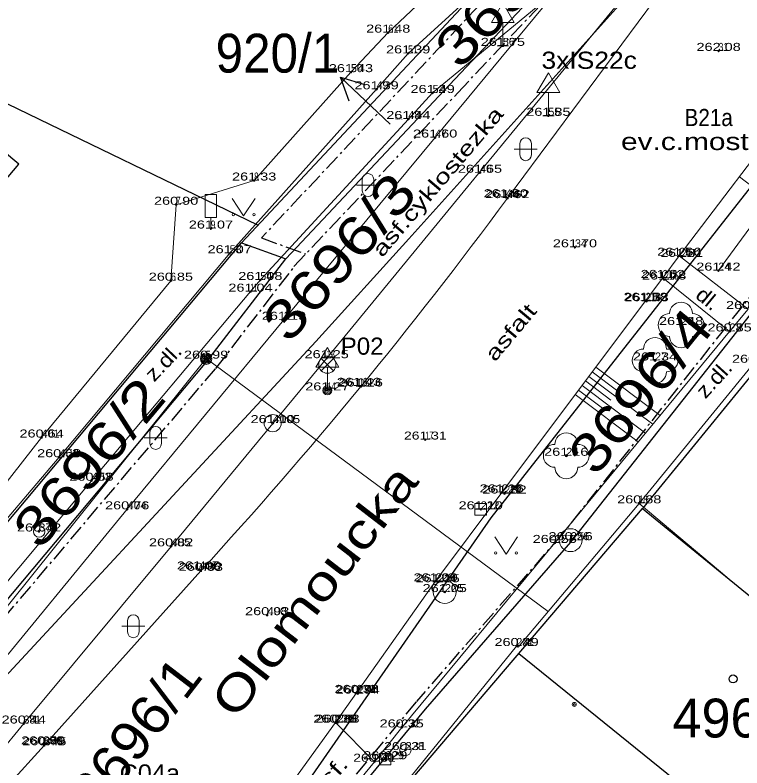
# Model space of a CAD drawing. Extents: x -568530 to -568223, y -1154101 to -1153740.
# Drawn here: x -568460.84 to -568429.07, y -1153975.43 to -1153942.5 of the extents above; entities that cross this region are included whole.
import ezdxf
from ezdxf.enums import TextEntityAlignment as Align

# ---------------------------------------------------------------- set-up
doc = ezdxf.new("R2010")
doc.units = 0
doc.header["$LTSCALE"] = 0.14
doc.header["$PDMODE"] = 32
doc.header["$PDSIZE"] = 0.07
doc.linetypes.add('DOT_DASHED', pattern=[7.7, 5, -1.2, 0.3, -1.2])
for name, color, linetype, lineweight in [('1', 7, 'Continuous', 25), ('10', 7, 'Continuous', 13), ('11', 7, 'Continuous', 13), ('12', 7, 'Continuous', 13), ('15', 7, 'Continuous', 13), ('21', 7, 'Continuous', 13), ('22', 7, 'Continuous', 13), ('23', 7, 'Continuous', 13), ('25', 7, 'Continuous', 13), ('27', 7, 'Continuous', 13), ('28', 7, 'Continuous', 13), ('33', 7, 'Continuous', 13), ('34', 7, 'Continuous', 13), ('36', 7, 'Continuous', 13), ('38', 7, 'Continuous', 13), ('39', 7, 'Continuous', 13), ('42', 7, 'Continuous', 13), ('5', 7, 'Continuous', 13), ('51', 7, 'Continuous', 13), ('6', 7, 'DOT_DASHED', 25), ('7', 7, 'Continuous', 13)]:
    doc.layers.add(name, color=color, linetype=linetype, lineweight=lineweight)
for name, color, linetype in [('13', 7, 'Continuous'), ('18', 7, 'Continuous'), ('19', 7, 'Continuous'), ('20', 7, 'Continuous'), ('40', 7, 'Continuous'), ('49', 7, 'Continuous')]:
    doc.layers.add(name, color=color, linetype=linetype)

msp = doc.modelspace()

# ---------------------------------------------------------------- linework, layer by layer
at = {"layer": '1'}
for p, q in [((-568450.23, -1153951.69), (-568463.93, -1153945.07)), ((-568450.95, -1153952.46), (-568449.01, -1153953.16)), ((-568443.46, -1153975.87), (-568433.42, -1153964.08)), ((-568438.82, -1153970.42), (-568429.77, -1153977.74))]:
    msp.add_line(p, q, dxfattribs=at)
for points in [[(-568415.28, -1153906.83), (-568416.25, -1153907.73), (-568417.28, -1153909.65), (-568429.7, -1153929.89), (-568430.98, -1153931.64), (-568432.38, -1153933.77), (-568434.43, -1153934.79), (-568436.25, -1153936.74), (-568450.95, -1153952.46)], [(-568474.2, -1153983.6), (-568452.46, -1153957.65), (-568449.01, -1153953.16), (-568441.85, -1153945.56), (-568434.01, -1153937.23), (-568430.2, -1153935.69), (-568428.09, -1153933.47), (-568426.88, -1153931.62), (-568414.57, -1153911.32), (-568413.31, -1153909.52)], [(-568421.22, -1153939.56), (-568428.14, -1153935.17), (-568430.26, -1153937.4), (-568443.63, -1153952.29), (-568447.7, -1153956.78), (-568470.49, -1153981.39)], [(-568416.35, -1153942.92), (-568421.22, -1153939.56), (-568427.43, -1153948.41), (-568440.04, -1153964.5), (-568454.41, -1153985.19), (-568457.74, -1153989.19)], [(-568465.85, -1153955.45), (-568463.4, -1153952.25), (-568460.68, -1153949.03), (-568464.54, -1153945.8), (-568464.79, -1153945.59), (-568466, -1153947.05)], [(-568421.83, -1153950.13), (-568423.36, -1153948.82), (-568436.57, -1153965.56)], [(-568421.83, -1153950.13), (-568427.7, -1153957.09), (-568433.42, -1153964.08), (-568426, -1153970.14), (-568416.24, -1153978.06), (-568413.96, -1153980.06), (-568408.2, -1153972.93), (-568413.31, -1153968.6), (-568420.22, -1153963.08), (-568427.7, -1153957.09)], [(-568498.47, -1153957.36), (-568472.48, -1153978.28), (-568467.49, -1153972.24), (-568464.36, -1153968.47), (-568450.95, -1153952.46)], [(-568436.57, -1153965.56), (-568442.92, -1153972.86), (-568448.69, -1153979.85), (-568458.57, -1153991.38), (-568456.99, -1153992.49)]]:
    msp.add_lwpolyline(points, dxfattribs=at)
at = {"layer": '10'}
for p, q in [((-568459.56, -1153974.44), (-568452.72, -1153966.81)), ((-568468.5, -1153984.3), (-568459.56, -1153974.44))]:
    msp.add_line(p, q, dxfattribs=at)
for points in [[(-568451.7, -1153980.29), (-568449.61, -1153977.28), (-568446.84, -1153973.45), (-568445.91, -1153972.15), (-568442.46, -1153967.27), (-568439.57, -1153963.38), (-568433.28, -1153955), (-568432.53, -1153954), (-568431.81, -1153953.03), (-568426.84, -1153946.5), (-568420.35, -1153937.98), (-568416.07, -1153932.32)], [(-568439.32, -1153950.51), (-568432.9, -1153941.84), (-568427.22, -1153934.12)]]:
    msp.add_lwpolyline(points, dxfattribs=at)
msp.add_arc((-568598.8003, -1153833.0615), 198.0609, 317.52333, 323.63038, dxfattribs=at)
at = {"layer": '11'}
for p, q in [((-568447.22, -1153957.51), (-568433.85, -1153941.21)), ((-568437.12, -1153941.38), (-568442.59, -1153945.91)), ((-568437.12, -1153941.38), (-568442.48, -1153947.86)), ((-568432.53, -1153954), (-568429.61, -1153956.34)), ((-568460.46, -1153973.49), (-568468.03, -1153982.68)), ((-568446.84, -1153973.45), (-568445.13, -1153975.16))]:
    msp.add_line(p, q, dxfattribs=at)
for points in [[(-568451.52, -1153952.97), (-568451.46, -1153952.92), (-568445.04, -1153945.75), (-568443.66, -1153944.18), (-568437.31, -1153938.38), (-568436.1, -1153937.25), (-568432.62, -1153934.09)], [(-568442.59, -1153945.91), (-568443.65, -1153947.05), (-568450.12, -1153954.09), (-568450.55, -1153954.6), (-568457.5, -1153962.87), (-568463.86, -1153970.48)], [(-568462.41, -1153971.99), (-568455.94, -1153964.12), (-568449.09, -1153955.83), (-568442.48, -1153947.86)], [(-568464.95, -1153968.94), (-568458.91, -1153961.84), (-568451.46, -1153952.92)], [(-568445.13, -1153975.16), (-568443.94, -1153973.66), (-568437.25, -1153965.59), (-568429.61, -1153956.34), (-568428.8, -1153955.36), (-568431.81, -1153953.03)], [(-568447.22, -1153957.51), (-568454.02, -1153965.74), (-568460.46, -1153973.49)], [(-568458.69, -1153991.53), (-568450.34, -1153981.46), (-568447.73, -1153978.32), (-568445.13, -1153975.16)]]:
    msp.add_lwpolyline(points, dxfattribs=at)
for p in [(-568444.53, -1153943.27), (-568439.52, -1153943.85), (-568443.66, -1153944.18), (-568430.09, -1153944.07), (-568446.16, -1153945), (-568445.04, -1153945.75), (-568442.59, -1153945.91), (-568443.65, -1153947.05), (-568437.53, -1153946.91), (-568442.48, -1153947.86), (-568440.52, -1153949.4), (-568450.39, -1153949.74), (-568439.39, -1153950.47), (-568439.32, -1153950.51), (-568453.8, -1153950.8), (-568452.28, -1153951.84), (-568436.37, -1153952.66), (-568451.46, -1153952.92), (-568431.81, -1153953.03), (-568431.7, -1153953.08), (-568430.1, -1153953.68), (-568454.03, -1153954.12), (-568450.12, -1153954.09), (-568432.53, -1153954), (-568432.47, -1153954.07), (-568450.55, -1153954.6), (-568433.28, -1153955), (-568433.24, -1153955.02), (-568449.09, -1153955.83), (-568431.73, -1153956.06), (-568429.61, -1153956.34), (-568452.49, -1153957.53), (-568447.22, -1153957.51), (-568432.87, -1153957.61), (-568445.81, -1153958.72), (-568447.19, -1153958.92), (-568445.73, -1153958.75), (-568459.68, -1153960.98), (-568442.91, -1153961.07), (-568458.91, -1153961.84), (-568436.75, -1153961.78), (-568457.5, -1153962.87), (-568439.57, -1153963.38), (-568439.45, -1153963.43), (-568433.56, -1153963.86), (-568455.94, -1153964.12), (-568440.49, -1153964.12), (-568459.79, -1153965.09), (-568437.25, -1153965.59), (-568436.56, -1153965.47), (-568454.02, -1153965.74), (-568452.8, -1153966.75), (-568452.72, -1153966.81), (-568442.46, -1153967.27), (-568442.37, -1153967.31), (-568442.06, -1153967.74), (-568449.82, -1153968.75), (-568438.92, -1153970.1), (-568445.91, -1153972.15), (-568445.86, -1153972.18), (-568460.46, -1153973.49), (-568446.84, -1153973.45), (-568446.75, -1153973.45), (-568443.94, -1153973.66), (-568459.61, -1153974.4), (-568459.56, -1153974.44), (-568443.78, -1153974.65), (-568445.13, -1153975.16), (-568444.66, -1153975.05)]:
    msp.add_point(p, dxfattribs=at)
at = {"layer": '15'}
for p, q in [((-568429.185, -1153949.58), (-568426.029, -1153951.982)), ((-568435.46, -1153957.905), (-568432.647, -1153960.017)), ((-568435.76, -1153958.305), (-568432.965, -1153960.403)), ((-568435.61, -1153958.105), (-568434.489, -1153958.947)), ((-568436.061, -1153958.705), (-568433.284, -1153960.788)), ((-568435.911, -1153958.505), (-568434.796, -1153959.341)), ((-568436.211, -1153958.904), (-568435.104, -1153959.735)), ((-568436.361, -1153959.104), (-568433.603, -1153961.174))]:
    msp.add_line(p, q, dxfattribs=at)
at = {"layer": '21'}
for radius in [0.375, 0.05]:
    msp.add_circle((-568449.58, -1153960.35), radius, dxfattribs=at)
at = {"layer": '22'}
for centre in [(-568431.73, -1153956.06), (-568432.87, -1153957.61), (-568436.75, -1153961.78)]:
    msp.add_circle(centre, 0.05, dxfattribs=at)
for centre, start, end in [((-568431.73, -1153955.56), 0, 180), ((-568432.23, -1153956.06), 90, 270), ((-568431.23, -1153956.06), 270, 90), ((-568432.87, -1153957.11), 0, 180), ((-568431.73, -1153956.56), 180, 0), ((-568433.37, -1153957.61), 90, 270), ((-568432.37, -1153957.61), 270, 90), ((-568432.87, -1153958.11), 180, 0), ((-568436.75, -1153961.28), 0, 180), ((-568437.25, -1153961.78), 90, 270), ((-568436.25, -1153961.78), 270, 90), ((-568436.75, -1153962.28), 180, 0)]:
    msp.add_arc(centre, 0.5, start, end, dxfattribs=at)
at = {"layer": '25', "lineweight": 25}
msp.add_line((-568444.44, -1153947.28), (-568446.623, -1153945.223), dxfattribs=at)
msp.add_lwpolyline([(-568446.238, -1153946.273), (-568446.623, -1153945.223), (-568445.552, -1153945.545)], dxfattribs=at)
at = {"layer": '25'}
for radius in [0.25, 0.2, 0.15, 0.1, 0.05]:
    msp.add_circle((-568452.49, -1153957.53), radius, dxfattribs=at)
at = {"layer": '25', "lineweight": 25}
msp.add_circle((-568429.46, -1153971.54), 0.175, dxfattribs=at)
at = {"layer": '27'}
for p, q in [((-568440.74, -1153964.12), (-568440.24, -1153964.12)), ((-568444.91, -1153975.05), (-568444.41, -1153975.05))]:
    msp.add_line(p, q, dxfattribs=at)
for points in [[(-568440.74, -1153964.37), (-568440.24, -1153964.37), (-568440.24, -1153963.87), (-568440.74, -1153963.87)], [(-568444.91, -1153975.3), (-568444.41, -1153975.3), (-568444.41, -1153974.8), (-568444.91, -1153974.8)]]:
    msp.add_lwpolyline(points, close=True, dxfattribs=at)
for centre in [(-568436.56, -1153965.47), (-568442.06, -1153967.74)]:
    msp.add_circle(centre, 0.5, dxfattribs=at)
at = {"layer": '28'}
for centre in [(-568459.79, -1153965.09), (-568443.78, -1153974.65)]:
    msp.add_circle(centre, 0.25, dxfattribs=at)
at = {"layer": '33'}
for p, q in [((-568447.455, -1153958.06), (-568446.925, -1153957.53)), ((-568447.455, -1153957.53), (-568446.925, -1153958.06)), ((-568447.19, -1153958.17), (-568447.19, -1153958.92))]:
    msp.add_line(p, q, dxfattribs=at)
for centre, radius in [((-568447.19, -1153957.795), 0.375), ((-568447.19, -1153958.92), 0.2), ((-568447.19, -1153958.92), 0.1445), ((-568447.19, -1153958.92), 0.0876)]:
    msp.add_circle(centre, radius, dxfattribs=at)
at = {"layer": '34'}
for p, q in [((-568439.52, -1153942.832), (-568439.52, -1153943.85)), ((-568439.77, -1153943.85), (-568439.27, -1153943.85)), ((-568437.53, -1153945.892), (-568437.53, -1153946.91)), ((-568437.78, -1153946.91), (-568437.28, -1153946.91)), ((-568447.19, -1153957.902), (-568447.19, -1153958.92))]:
    msp.add_line(p, q, dxfattribs=at)
for points in [[(-568440.02, -1153942.832), (-568439.02, -1153942.832), (-568439.52, -1153941.966)], [(-568438.03, -1153945.892), (-568437.03, -1153945.892), (-568437.53, -1153945.026)], [(-568447.69, -1153957.902), (-568446.69, -1153957.902), (-568447.19, -1153957.036)]]:
    msp.add_lwpolyline(points, close=True, dxfattribs=at)
at = {"layer": '36'}
for p, q in [((-568438.774, -1153948.121), (-568438.774, -1153948.621)), ((-568438.274, -1153948.121), (-568438.274, -1153948.621)), ((-568439.024, -1153948.371), (-568438.024, -1153948.371)), ((-568445.664, -1153949.686), (-568445.664, -1153950.186)), ((-568445.164, -1153949.686), (-568445.164, -1153950.186)), ((-568445.914, -1153949.936), (-568444.914, -1153949.936)), ((-568455.194, -1153960.997), (-568454.194, -1153960.997)), ((-568454.944, -1153960.747), (-568454.944, -1153961.247)), ((-568454.444, -1153960.747), (-568454.444, -1153961.247)), ((-568456.173, -1153969.235), (-568455.173, -1153969.235)), ((-568455.923, -1153968.985), (-568455.923, -1153969.485)), ((-568455.423, -1153968.985), (-568455.423, -1153969.485))]:
    msp.add_line(p, q, dxfattribs=at)
for points in [[(-568451.35, -1153950.532), (-568450.85, -1153951.282), (-568450.35, -1153950.532)], [(-568439.878, -1153965.327), (-568439.378, -1153966.077), (-568438.878, -1153965.327)]]:
    msp.add_lwpolyline(points, dxfattribs=at)
for centre in [(-568451.3006, -1153951.2321), (-568450.4012, -1153951.2321), (-568439.8285, -1153966.0273), (-568438.9291, -1153966.0273)]:
    msp.add_circle(centre, 0.05, dxfattribs=at)
for centre, start, end in [((-568438.5235, -1153948.1214), 0, 180), ((-568438.5235, -1153948.6214), 180, 0), ((-568445.4139, -1153949.6868), 0, 180), ((-568445.4139, -1153950.1868), 180, 0), ((-568454.6934, -1153960.7477), 0, 180), ((-568454.6934, -1153961.2477), 180, 0), ((-568455.6725, -1153968.9857), 0, 180), ((-568455.6725, -1153969.4857), 180, 0)]:
    msp.add_arc(centre, 0.25, start, end, dxfattribs=at)
at = {"layer": '38'}
msp.add_line((-568452.28, -1153951.355), (-568452.28, -1153951.84), dxfattribs=at)
msp.add_lwpolyline([(-568452.53, -1153951.355), (-568452.03, -1153951.355), (-568452.03, -1153950.355), (-568452.53, -1153950.355)], close=True, dxfattribs=at)
at = {"layer": '39'}
for radius in [0.09, 0.0398]:
    msp.add_circle((-568436.3997, -1153972.6525), radius, dxfattribs=at)
at = {"layer": '5'}
for p, q in [((-568438.858, -1153970.15), (-568433.56, -1153963.86)), ((-568438.92, -1153970.1), (-568443.53, -1153975.79)), ((-568438.858, -1153970.15), (-568438.92, -1153970.1))]:
    msp.add_line(p, q, dxfattribs=at)
msp.add_lwpolyline([(-568429.736, -1153967.081), (-568433.56, -1153963.86), (-568428.54, -1153957.71), (-568427.1, -1153956.02), (-568421.95, -1153949.83), (-568414.4, -1153956.01)], dxfattribs=at)
at = {"layer": '51'}
msp.add_lwpolyline([(-568486.26, -1153993.13), (-568470.55, -1153980.04), (-568452.49, -1153957.53), (-568437.543, -1153968.589)], dxfattribs=at)
at = {"layer": '6'}
for p, q in [((-568435.89, -1153937.08), (-568450.07, -1153952.25)), ((-568423.43, -1153948.11), (-568436.96, -1153965.25)), ((-568450.07, -1153952.25), (-568448.13, -1153952.95)), ((-568452.06, -1153957.96), (-568448.61, -1153953.47)), ((-568470.89, -1153980.16), (-568452.08, -1153957.97)), ((-568436.95, -1153965.23), (-568443.3, -1153972.53)), ((-568443.31, -1153972.54), (-568449.08, -1153979.53))]:
    msp.add_line(p, q, dxfattribs=at)
msp.add_lwpolyline([(-568448.65, -1153953.5), (-568441.49, -1153945.9), (-568433.65, -1153937.57), (-568430.36, -1153934.31), (-568428.41, -1153935.59)], dxfattribs=at)
at = {"layer": '7'}
for points in [[(-568437.06, -1153936.21), (-568444.53, -1153943.27), (-568446.16, -1153945), (-568450.39, -1153949.74)], [(-568430.1, -1153953.68), (-568425.5, -1153947.42), (-568422.23, -1153943.29)], [(-568450.39, -1153949.74), (-568453.8, -1153950.8), (-568454.03, -1153954.12), (-568459.68, -1153960.98), (-568461.83, -1153963.7)]]:
    msp.add_lwpolyline(points, dxfattribs=at)

# ---------------------------------------------------------------- texts
at = {"layer": '12'}
for s, width, p in [('261.48', 1.35, (-568444.53, -1153943.27)), ('261.75', 1.35, (-568439.5205, -1153943.85)), ('261.39', 1.35, (-568443.66, -1153944.18)), ('262.08', 1.35, (-568430.09, -1153944.07)), ('261.43', 1.35, (-568446.16, -1153945)), ('261.39', 1.35, (-568445.04, -1153945.75)), ('261.49', 1.35, (-568442.59, -1153945.91)), ('261.44', 1.35, (-568443.65, -1153947.05)), ('261.85', 1.35, (-568437.5305, -1153946.91)), ('261.60', 1.35, (-568442.4795, -1153947.86)), ('261.65', 1.35, (-568440.5205, -1153949.4)), ('261.33', 1.35, (-568450.39, -1153949.74)), ('261.80', 1.35, (-568439.3895, -1153950.47)), ('260.90', 1.35, (-568453.7995, -1153950.8)), ('261.62', 1.35, (-568439.32, -1153950.51)), ('261.07', 1.35, (-568452.28, -1153951.84)), ('261.70', 1.35, (-568436.3695, -1153952.66)), ('261.07', 1.35, (-568451.46, -1153952.92)), ('261.66', 1.35, (-568431.81, -1153953.03)), ('261.81', 1.3, (-568431.7, -1153953.08)), ('261.42', 1.35, (-568430.1, -1153953.68)), ('260.85', 1.35, (-568454.0305, -1153954.12)), ('261.08', 1.35, (-568450.12, -1153954.09)), ('261.62', 1.35, (-568432.53, -1153954)), ('261.78', 1.35, (-568432.47, -1153954.07)), ('261.04', 1.35, (-568450.55, -1153954.6)), ('261.58', 1.35, (-568433.28, -1153955)), ('261.73', 1.35, (-568433.24, -1153955.02)), ('260.88', 1.35, (-568428.8, -1153955.36)), ('261.19', 1.35, (-568449.09, -1153955.83)), ('261.48', 1.35, (-568431.73, -1153956.06)), ('260.85', 1.35, (-568429.6105, -1153956.34)), ('260.99', 1.35, (-568452.49, -1153957.53)), ('261.25', 1.35, (-568447.2205, -1153957.51)), ('261.34', 1.35, (-568432.87, -1153957.61)), ('260.84', 1.35, (-568428.54, -1153957.71)), ('261.43', 1.35, (-568445.81, -1153958.72)), ('261.27', 1.35, (-568447.19, -1153958.92)), ('261.26', 1.35, (-568445.73, -1153958.75)), ('260.64', 1.35, (-568459.68, -1153960.98)), ('261.31', 1.3, (-568442.91, -1153961.07)), ('260.59', 1.35, (-568458.91, -1153961.84)), ('261.16', 1.35, (-568436.75, -1153961.78)), ('260.58', 1.35, (-568457.5, -1153962.87)), ('261.16', 1.35, (-568439.57, -1153963.38)), ('261.32', 1.35, (-568439.45, -1153963.43)), ('260.68', 1.35, (-568433.56, -1153963.86)), ('260.76', 1.35, (-568455.94, -1153964.12)), ('261.10', 1.35, (-568440.4895, -1153964.12)), ('260.42', 1.35, (-568459.79, -1153965.09)), ('260.55', 1.35, (-568437.2505, -1153965.59)), ('260.56', 1.35, (-568436.56, -1153965.47)), ('260.82', 1.35, (-568454.02, -1153965.74)), ('261.00', 1.35, (-568452.7995, -1153966.75)), ('260.83', 1.35, (-568452.72, -1153966.81)), ('261.00', 1.35, (-568442.4595, -1153967.27)), ('261.15', 1.35, (-568442.3705, -1153967.31)), ('261.05', 1.35, (-568442.0605, -1153967.74)), ('260.93', 1.35, (-568449.82, -1153968.75)), ('260.49', 1.35, (-568438.92, -1153970.1)), ('260.78', 1.35, (-568445.91, -1153972.15)), ('260.94', 1.35, (-568445.86, -1153972.18)), ('260.44', 1.35, (-568460.46, -1153973.49)), ('260.73', 1.35, (-568446.84, -1153973.45)), ('260.88', 1.35, (-568446.75, -1153973.45)), ('260.35', 1.35, (-568443.9405, -1153973.66)), ('260.59', 1.35, (-568459.61, -1153974.4)), ('260.45', 1.35, (-568459.5605, -1153974.44)), ('260.31', 1.3, (-568443.78, -1153974.65)), ('260.31', 1.3, (-568445.13, -1153975.16)), ('260.29', 1.35, (-568444.66, -1153975.05))]:
    msp.add_text(s, height=0.35, dxfattribs=dict(at, width=width)).set_placement(p, align=Align.CENTER)
at = {"layer": '13'}
for s, width, p in [('61', 0.85, (-568444.53, -1153943.27)), ('51', 0.8, (-568443.66, -1153944.18)), ('31', 0.8, (-568430.09, -1153944.07)), ('8', 0.75, (-568450.39, -1153949.74)), ('7', 0.75, (-568453.8, -1153950.8)), ('9', 0.75, (-568452.28, -1153951.84)), ('217', 0.8, (-568431.7, -1153953.08)), ('6', 0.85, (-568454.03, -1153954.12)), ('215', 0.8, (-568432.53, -1153954)), ('216', 0.8, (-568432.47, -1153954.07)), ('11', 0.45, (-568450.55, -1153954.6)), ('218', 0.8, (-568433.28, -1153955)), ('219', 0.8, (-568433.24, -1153955.02)), ('12', 0.6, (-568449.09, -1153955.83)), ('5', 0.75, (-568452.49, -1153957.53)), ('13', 0.6, (-568447.22, -1153957.51)), ('16', 0.65, (-568445.81, -1153958.72)), ('14', 0.6, (-568447.19, -1153958.92)), ('15', 0.6, (-568445.73, -1153958.75)), ('17', 0.6, (-568442.91, -1153961.07)), ('402', 1.1, (-568458.91, -1153961.84)), ('403', 1.1, (-568457.5, -1153962.87)), ('220', 1.1, (-568439.57, -1153963.38)), ('221', 0.95, (-568439.45, -1153963.43)), ('18', 0.6, (-568433.56, -1153963.86)), ('404', 1.1, (-568455.94, -1153964.12)), ('222', 1.05, (-568440.49, -1153964.12)), ('378', 1.05, (-568459.79, -1153965.09)), ('227', 1.05, (-568437.25, -1153965.59)), ('226', 1.05, (-568436.56, -1153965.47)), ('405', 1.1, (-568454.02, -1153965.74)), ('407', 1.1, (-568452.8, -1153966.75)), ('406', 1.1, (-568452.72, -1153966.81)), ('223', 1.05, (-568442.46, -1153967.27)), ('224', 1.05, (-568442.37, -1153967.31)), ('225', 1.05, (-568442.06, -1153967.74)), ('408', 1.1, (-568449.82, -1153968.75)), ('231', 0.95, (-568438.92, -1153970.1)), ('233', 1.05, (-568445.91, -1153972.15)), ('234', 1.05, (-568445.86, -1153972.18)), ('381', 0.95, (-568460.46, -1153973.49)), ('235', 1.05, (-568446.84, -1153973.45)), ('236', 1.05, (-568446.75, -1153973.45)), ('232', 1.05, (-568443.94, -1153973.66)), ('380', 1.1, (-568459.61, -1153974.4)), ('379', 1.05, (-568459.56, -1153974.44)), ('228', 1.05, (-568443.78, -1153974.65)), ('240', 1.1, (-568445.13, -1153975.16)), ('229', 1.05, (-568444.66, -1153975.05))]:
    msp.add_text(s, height=0.35, dxfattribs=dict(at, width=width)).set_placement(p)
for s, p in [('56', (-568439.52, -1153943.85)), ('50', (-568446.16, -1153945)), ('49', (-568445.04, -1153945.75)), ('52', (-568442.59, -1153945.91)), ('48', (-568443.65, -1153947.05)), ('55', (-568437.53, -1153946.91)), ('47', (-568442.48, -1153947.86)), ('46', (-568440.52, -1153949.4)), ('45', (-568439.39, -1153950.47)), ('44', (-568439.32, -1153950.51)), ('34', (-568436.37, -1153952.66)), ('53', (-568451.46, -1153952.92)), ('25', (-568431.81, -1153953.03)), ('24', (-568430.1, -1153953.68)), ('54', (-568450.12, -1153954.09)), ('26', (-568431.73, -1153956.06)), ('23', (-568429.61, -1153956.34)), ('27', (-568432.87, -1153957.61)), ('401', (-568459.68, -1153960.98)), ('28', (-568436.75, -1153961.78))]:
    msp.add_text(s, height=0.35, dxfattribs=at).set_placement(p)
at = {"layer": '18'}
for s, rotation, width, p in [('3696/9', 46.5, 1.25, (-568441.407, -1153944.938)), ('3696/3', 49.1, 1.25, (-568448.87, -1153956.918)), ('3696/4', 51.2, 1.2, (-568435.46, -1153962.729)), ('3696/2', 50, 1.25, (-568459.754, -1153965.949)), ('3696/1', 52.5, 1.1, (-568457.236, -1153977.51))]:
    msp.add_text(s, height=1.7, rotation=rotation, dxfattribs=dict(at, width=width)).set_placement(p)
at = {"layer": '19'}
msp.add_text('496/2', height=1.7, dxfattribs=at).set_placement((-568432.1, -1153974.1))
at = {"layer": '20', "width": 0.95}
msp.add_text('920/1', height=1.7, dxfattribs=at).set_placement((-568446.671, -1153945.02), align=Align.RIGHT)
msp.add_text('920/1', height=0.1, dxfattribs=at).set_placement((-568444.24, -1153947.08))
at = {"layer": '22', "width": 1.35}
msp.add_text('261.10', height=0.35, dxfattribs=at).set_placement((-568449.5795, -1153960.35), align=Align.CENTER)
at = {"layer": '23', "width": 1.15}
msp.add_text('4005', height=0.35, dxfattribs=at).set_placement((-568449.58, -1153960.35))
at = {"layer": '40'}
for s, rotation, width, p in [('asf.cyklostezka', 49.573, 1.4, (-568444.796, -1153953.138)), ('dl.', 320.655, 1.1, (-568431.151, -1153954.838)), ('asfalt', 50.073, 1.4, (-568439.866, -1153957.702)), ('z.dl.', 46.41, 1.15, (-568454.761, -1153958.58)), ('z.dl.', 47.739, 1.15, (-568430.67, -1153959.322)), ('asf.', 47.739, 1.45, (-568447.599, -1153976.811))]:
    msp.add_text(s, height=0.65, rotation=rotation, dxfattribs=dict(at, width=width)).set_placement(p)
at = {"layer": '42'}
for s, width, p in [('3xIS22c', 1.15, (-568435.7475, -1153944.854)), ('B21a', 0.9, (-568430.5235, -1153947.358)), ('ev.c.mostu', 1.3, (-568431.204, -1153948.406)), ('P02', 1.05, (-568445.6705, -1153957.358)), ('C04a', 1.1, (-568454.9535, -1153976.027))]:
    msp.add_text(s, height=0.75, dxfattribs=dict(at, width=width)).set_placement(p, align=Align.CENTER)
at = {"layer": '49', "width": 1.3}
msp.add_text('Olomoucka', height=1.5, rotation=52.355, dxfattribs=at).set_placement((-568451.195, -1153973.362))

doc.saveas('drawing.dxf')
